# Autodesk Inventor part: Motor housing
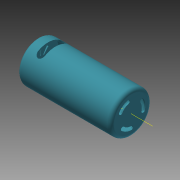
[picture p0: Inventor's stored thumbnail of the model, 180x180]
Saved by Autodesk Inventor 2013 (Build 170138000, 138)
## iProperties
Created: 2008-06
Part Number: Motor housing
Document SubType Name: Modeling
Designer: tangg
Density: 1.13 g/cm^3
Mass: 14.7217 g
Surface Area: 216.806 cm^2
Volume: 14.7217 cm^3
Stock Number: Motor housing
Material: Nylon-6/6
Author: tangg
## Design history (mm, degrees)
sketch "Sketch1"
  geometry: L1 (0, 0)-(82.55, 0); L2 (0, 0)-(0, 18.503); L3 (82.55, 18.503)-(82.55, 0); L4 (82.55, 18.503)-(82.55, 9.252); L5 (0, 18.503)-(82.55, 18.503); 1 further point
  constraints: 10 end point, 2 horizontal, 2 vertical, 1 midpoint, 1 point on line
  dimensions: "d13" = 82.55 distance of L2.end L3.start
revolve "Revolution1" sketch "Sketch1" stored, may be unused: angle "d0" = 90 deg
fillet "Fillet1" dims "d1" = 3.175
shell "Shell1" dims "d6" = 1.27
sketch "Sketch3"
  geometry: L1 (0, 0)-(10.999, 6.35); L2 (0, 0)-(12.267, -3.287); L3 (8.249, 4.762)-(10.999, 6.35); L4 (9.2, -2.465)-(12.267, -3.287); A1 r 9.525 centre (0, 0) between (9.2, -2.465) and (8.249, 4.762); A2 r 12.7 centre (0, 0) between (12.267, -3.287) and (10.999, 6.35); A3 r 1.588 centre (10.734, -2.876) between (9.2, -2.465) and (12.267, -3.287); 2 further points
  constraints: 8 end point, 6 point on circle, 3 centre point, 2 coincident, 2 midpoint, 2 point on line, 3 other
  dimensions: "d2" = 45 deg angle of L2 L1
extrude "Extrusion1" cut sketch "Sketch3" distance "d3" = 2.54; taper "d4" = 0 deg
workplane "Work Plane2"
sketch "Sketch4"
  geometry: 1 further point
pattern_circular "Circular Pattern1" dims angle "d8" = 360 deg
sketch "Sketch5"
  geometry: 1 further point
sketch "Sketch6"
  geometry: C1 r 17.233 at (0, 0) reference; C2 r 18.503 at (0, 0) reference; 1 further point
extrude "Extrusion2" join sketch "Sketch6" distance "d10" = 2.54; taper "d11" = 0 deg
fillet "Fillet2" dims "d12" = 3.175
sketch "Sketch7"
  geometry: L1 (-6.946, 8.998)-(-6.946, -8.998); L2 (16.51, 0)-(-99.06, 0) reference; L3 (-13.615, 8.731)-(-13.615, -8.731); A1 r 3.345 centre (-10.29, 9.095) between (-6.946, 8.998) and (-13.615, 8.731); A2 r 3.34 centre (-10.275, -8.731) between (-13.615, -8.731) and (-6.946, -8.998); 3 further points
  constraints: 4 end point, 4 point on circle, 2 centre point, 2 midpoint, 2 point on line
extrude "Extrusion3" cut sketch "Sketch7" stored distance "d14" = 25.4; taper "d15" = 0 deg
workplane "Work Plane4"
  workplane "Work Plane3"
sketch "Sketch8"
  geometry: L1 (26.988, -22.225)-(6.565, -22.196); L2 (6.565, -22.196)-(6.57, -19.01); L3 (6.57, -19.01)-(26.992, -19.039); L4 (26.992, -19.039)-(26.988, -22.225); 1 further point
  constraints: 2 other
  dimensions: "d17" = 3.18632 distance of L1.end L2.end; "d18" = 20.42209 distance of L2.end L3.end
emboss "Emboss1" sketch "Sketch8" dims "d19" = 0.254, "d20" = 0
sketch "Sketch9"
  geometry: L1 (0, 0)-(1.167, 14.833); L2 (0, 0)-(-1.266, 16.086); L3 (0, 25.904)-(0, -25.904) reference; L4 (-0.374, 4.748)-(-0.875, 11.113); L5 (0.374, 4.748)-(0.875, 11.113); A1 r 4.763 centre (0, 0) between (-0.374, 4.748) and (0.374, 4.748); A2 r 11.147 centre (0, 0) between (0.875, 11.113) and (-0.875, 11.113); A3 r 4.762 centre (0, 0) between (0.374, 4.748) and (-0.374, 4.748); 1 further point
  constraints: 8 end point, 6 point on circle, 4 point on line, 3 centre point, 2 coincident, 3 other
  dimensions: "d21" = 9 deg angle of L1 L2; "d22" = 4.5 deg angle of L1 L3
extrude "Extrusion4" cut sketch "Sketch9" stored distance "d23" = 10; taper "d24" = 0 deg
pattern_circular "Circular Pattern2" dims angle "d26" = 360 deg
body "Solid1"
workaxis "Work Axis1"
workaxis "Work Axis2"
node "Projected Loop1"
other parameters: "d5" = -3.81, "d16" = 60 deg
